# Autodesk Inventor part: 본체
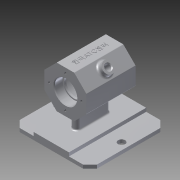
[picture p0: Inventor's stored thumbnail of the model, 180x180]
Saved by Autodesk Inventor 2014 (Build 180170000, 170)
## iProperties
Created: 2018-06
Part Number: 본체
Material: Aluminum 6061
Document SubType Name: Modeling
Designer: kh
Density: 2.71 g/cm^3
Appearance: Aluminum - Flat
Mass: 554.078 g
Surface Area: 602.069 cm^2
Volume: 204.457 cm^3
Author: kh
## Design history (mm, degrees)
sketch "Sketch1"
  geometry: 1 further point
sketch "Sketch2"
  geometry: L1 (-55, -55)-(55, -55); L2 (55, -55)-(55, 55); L3 (55, 55)-(-55, 55); L4 (-55, 55)-(-55, -55); L5 (-55, -55)-(55, 55); L6 (55, -55)-(-55, 55); 1 further point
  constraints: 12 end point, 2 midpoint, 2 parallel, 1 horizontal, 1 perpendicular
  dimensions: "d0" = 110 distance of L2.end L3.end; "d1" = 110 distance of L1.end L2.end
extrude "Extrusion1" new body sketch "Sketch2" distance "d2" = 5; taper "d3" = 0 deg
sketch "Sketch3"
  geometry: L1 (-55, 55)-(-55, -55) reference; L2 (55, -55)-(55, 55) reference; L3 (-55, -25)-(55, -25); L4 (55, -25)-(55, 25); L5 (55, 25)-(-55, 25); L6 (-55, 25)-(-55, -25); L7 (-55, -25)-(55, 25); L8 (55, -25)-(-55, 25); L9 (55, 55)-(-55, 55) reference; L10 (-55, -55)-(55, -55) reference; 1 further point
  constraints: 12 end point, 2 midpoint, 2 parallel, 1 horizontal, 1 perpendicular, 1 point on line
  dimensions: "d4" = 30 distance between parallel lines of L9 L5
extrude "Extrusion2" join sketch "Sketch3" distance "d5" = 5; taper "d6" = 0 deg
sketch "Sketch4"
  geometry: 1 further point
sketch "Sketch5" dims "d7" = 60
  geometry: L1 (12.426, 92)-(30, 74.426); L2 (30, 74.426)-(30, 49.574); L3 (30, 49.574)-(12.426, 32); L4 (12.426, 32)-(-12.426, 32); L5 (-12.426, 32)-(-30, 49.574); L6 (-30, 49.574)-(-30, 74.426); L7 (-30, 74.426)-(-12.426, 92); L8 (-12.426, 92)-(12.426, 92); 4 further points
  constraints: 16 end point, 2 vertical alignment, 1 coincident, 1 midpoint, 19 other
  dimensions: "d10" = 62 distance of point (0, 62) point (0, 0); "d12" = 17.57359 horizontal distance of L1.start L1.end
extrude "Extrusion3" join sketch "Sketch5" stored distance "d13" = 70; taper "d14" = 0 deg
sketch "Sketch6"
  geometry: 1 further point
sketch "Sketch7" dims "d15" = 46
  geometry: L1 (-74.426, 30)-(-92, 12.426) reference; L2 (-92, 12.426)-(-92, -12.426) reference; L3 (-92, -12.426)-(-74.426, -30) reference; L4 (-74.426, -30)-(-49.574, -30) reference; L5 (-49.574, -30)-(-32, -12.426) reference; L6 (-32, -12.426)-(-32, 12.426) reference; L7 (-32, 12.426)-(-49.574, 30) reference; L8 (-49.574, 30)-(-74.426, 30) reference; L9 (-49.574, 30)-(-74.426, -30); L10 (-74.426, 30)-(-49.574, -30); L11 (-92, -12.426)-(-32, 12.426); L12 (-62, 0)-(-85, 0); C1 r 16 at (-62, 0); 2 further points
  constraints: 8 end point, 2 coincident, 1 centre point, 1 horizontal alignment, 1 midpoint, 1 parallel, 1 perpendicular, 1 point on line, 2 other
  dimensions: "d34" = 32 diameter of C1
  node "Projected Loop1"
hole "Hole1" sketch "Sketch7" diameter "d16" = 3.242; stored, may be unused: countersink angle "d20" = 90 deg, drill point angle "d22" = 118 deg; dims "d17" = 8, "d18" = 4, "d19" = 2, "d21" = 10
sketch "Sketch11"
  geometry: L1 (55, 55)-(-55, 55) reference; L2 (-55, -55)-(55, -55) reference; C1 r 5 at (0, 45); 1 further point
  constraints: 1 centre point, 1 vertical alignment
  dimensions: "d25" = 10 diameter of C1; "d26" = 10 distance from line of L1 C1.centre
extrude "Extrusion4" cut sketch "Sketch11" stored distance "d27" = 70; taper "d28" = 0 deg
mirror "Mirror1"
sketch "Sketch12"
  geometry: L1 (19, 0)-(-19, 0); L2 (19, 5)-(-19, 5); L3 (-19, -5)-(19, -5); A1 r 5 centre (19, 0) between (19, -5) and (19, 5); A2 r 5 centre (-19, 0) between (-19, 5) and (-19, -5); 1 further point
  constraints: 8 end point, 4 point on circle, 4 tangent, 2 centre point, 1 horizontal, 1 midpoint, 1 parallel
  dimensions: "d29" = 38 distance of L1.end L1.start; "d30" = 5 radius of A1
extrude "Extrusion5" join sketch "Sketch12" stored distance "d31" = 70; taper "d32" = 0 deg
fillet "Fillet1" dims "d33" = 2
extrude "Extrusion6" cut sketch "Sketch7" distance "d35" = 12; taper "d36" = 0 deg
pattern_circular "Circular Pattern1" dims angle "d38" = 360 deg
hole "Hole2" diameter "d43" = 28; stored, may be unused: countersink angle "d47" = 90 deg, drill point angle "d49" = 0 deg; dims "d41" = 10, "d42" = 10, "d44" = 8, "d45" = 4, "d46" = 2, "d48" = 3
sketch "Sketch16"
  geometry: L1 (-30, -12.426)-(-30, 12.426) reference; L2 (-30, 12.426)-(-12.426, 30) reference; L3 (-12.426, 30)-(12.426, 30) reference; L4 (12.426, 30)-(30, 12.426) reference; L5 (30, 12.426)-(30, -12.426) reference; L6 (30, -12.426)-(12.426, -30) reference; L7 (12.426, -30)-(-12.426, -30) reference; L8 (-12.426, -30)-(-30, -12.426) reference; L9 (-30, -12.426)-(-30, 12.426) reference; L10 (-30, 12.426)-(30, -12.426); L11 (30, 12.426)-(-30, -12.426); C1 r 25 at (0, 0); 2 further points
  constraints: 4 end point, 3 midpoint, 1 centre point, 1 coincident, 1 point on line
  dimensions: "d50" = 50 diameter of C1
extrude "Extrusion7" cut sketch "Sketch16" distance "d51" = 40; taper "d52" = 0 deg
mirror "Mirror2"
mirror "Mirror3"
workplane "Work Plane2"
sketch "Sketch18"
  geometry: L1 (70, 24.853)-(0, 24.853) reference; L2 (0, 0)-(70, 0) reference; L3 (70, 24.853)-(70, 0) reference; L4 (0, 0)-(0, 24.853) reference; L5 (0, 12.426)-(83.367, 12.426); C1 r 8 at (35, 12.426); 1 further point
  constraints: 2 end point, 1 centre point, 1 midpoint, 1 perpendicular, 1 point on line
  dimensions: "d55" = 16 diameter of C1; "d56" = 35 distance from line of L3 C1.centre
extrude "Extrusion8" join sketch "Sketch18" stored distance "d59" = 40; taper "d60" = 0 deg
sketch "Sketch19"
  geometry: C1 r 8 at (0, 0) reference; C2 r 4 at (0, 0); 1 further point
  constraints: 1 centre point, 1 coincident
  dimensions: "d61" = 8 diameter of C2
extrude "Extrusion9" cut sketch "Sketch19" stored distance "d62" = 8 (= d61); taper "d63" = 0 deg
fillet "Fillet2" dims "d64" = 1
fillet "Fillet3" dims "d65" = 3
chamfer "Chamfer1" distance "d66" = 10; stored, may be unused: second distance "d67" = 2, angle "d68" = 45 deg
sketch "Sketch21"
  geometry: L1 (70, -17.695)-(0, -17.695) reference; L2 (70, -0.707)-(70, -17.695) reference; 2 further points
  constraints: 1 other
  dimensions: "d72" = 30 distance from line of L1 point (35, 12.305); "d73" = 35 distance from line of L2 point (35, 12.305)
emboss "Emboss1" sketch "Sketch21" dims "d74" = 0.5, "d75" = 0
chamfer "Chamfer2" distance "d76" = 1; stored, may be unused: second distance "d77" = 2, angle "d78" = 45 deg
fillet "Fillet4" dims "d79" = 0.3
fillet "Fillet5" dims "d80" = 3
chamfer "Chamfer3" distance "d81" = 1; stored, may be unused: second distance "d82" = 2, angle "d83" = 45 deg
body "Solid1"
node "Projected Loop3"
other parameters: "d54" = 7
